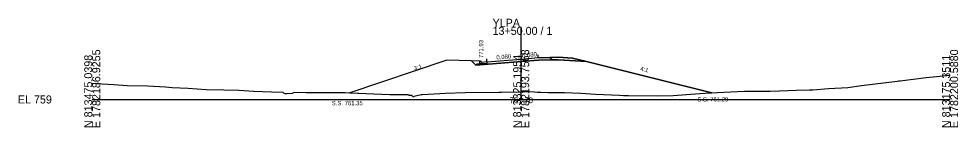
# Model space of a CAD drawing. Extents: x -76 to 1303, y -10 to 9544.
# Drawn here: x -25.7 to 302.8, y 3490.3 to 3528.2 of the extents above; entities that cross this region are included whole.
import ezdxf

# ---------------------------------------------------------------- set-up
doc = ezdxf.new("R2010")
doc.units = 0
for name, color, linetype in [('Exist Cross Section Cell', 7, 'Continuous'), ('Exist XS Center Line Elevation Label', 7, 'Continuous'), ('Exist XS Ground Line', 7, 'Continuous'), ('Prop XS Dump Level', 7, 'Continuous'), ('Prop XS Earthwork Shape', 7, 'Continuous'), ('Prop XS EOT Tick Mark', 7, 'Continuous'), ('Prop XS Finish Grade', 7, 'Continuous'), ('Prop XS Finish Grade CurbGutter', 7, 'Continuous'), ('Prop XS Finish Grade Earthwork', 7, 'Continuous'), ('Prop XS Finish Grade Paved Shoulder', 7, 'Continuous'), ('Prop XS Finish Grade Pavement', 7, 'Continuous'), ('Prop XS Hydro Elevations', 7, 'Continuous'), ('Prop XS Pvmt Edge Slope', 7, 'Continuous'), ('Prop XS SE Text', 7, 'Continuous'), ('Prop XS Side Slope Text', 7, 'Continuous'), ('Prop XS SS Elevation Text', 7, 'Continuous'), ('Prop XS Subgrade CurbGutter', 7, 'Continuous'), ('Prop XS Subgrade Earthwork', 7, 'Continuous'), ('Scratch_Level_3', 7, 'Continuous')]:
    doc.layers.add(name, color=color, linetype=linetype)

msp = doc.modelspace()

# ---------------------------------------------------------------- linework, layer by layer
at = {"layer": 'Exist Cross Section Cell'}
for p, q in [((150, 3500), (150, 3525.37)), ((0, 3500), (150, 3500)), ((150, 3500), (300, 3500))]:
    msp.add_line(p, q, dxfattribs=at)
at = {"layer": 'Exist XS Ground Line'}
for p, q in [((0, 3505.64), (1.39, 3505.58)), ((1.39, 3505.58), (7.54, 3505.21)), ((269, 3504.86), (281.44, 3506.4)), ((281.44, 3506.4), (282.06, 3506.48)), ((282.06, 3506.48), (282.5, 3506.53)), ((282.5, 3506.53), (291.68, 3507.67)), ((291.68, 3507.67), (300, 3508.46)), ((7.54, 3505.21), (12.25, 3504.91)), ((12.25, 3504.91), (19.31, 3504.73)), ((19.31, 3504.73), (25.63, 3504.38)), ((25.63, 3504.38), (27.94, 3504.15)), ((27.94, 3504.15), (33.5, 3503.96)), ((33.5, 3503.96), (39.79, 3503.5)), ((39.79, 3503.5), (45.96, 3503.41)), ((45.96, 3503.41), (51.38, 3503.19)), ((51.38, 3503.19), (56.36, 3502.88)), ((56.36, 3502.88), (62.74, 3502.68)), ((62.74, 3502.68), (66.64, 3502.6)), ((66.64, 3502.6), (66.99, 3502.18)), ((66.99, 3502.18), (67.32, 3502.03)), ((70.18, 3502.15), (70.39, 3502.39)), ((70.39, 3502.39), (70.9, 3502.52)), ((70.9, 3502.52), (74.79, 3502.45)), ((74.79, 3502.45), (84.25, 3502.37)), ((84.25, 3502.37), (86.65, 3502.47)), ((86.65, 3502.47), (88.42, 3502.43)), ((88.42, 3502.43), (95.71, 3502.05)), ((115.51, 3501.69), (123.57, 3502.23)), ((123.57, 3502.23), (130.36, 3502.41)), ((130.36, 3502.41), (142.26, 3502.58)), ((142.26, 3502.58), (142.64, 3502.58)), ((142.64, 3502.58), (143.14, 3502.59)), ((143.14, 3502.59), (150, 3502.7)), ((150, 3502.7), (152.94, 3502.74)), ((152.94, 3502.74), (154.66, 3502.62)), ((154.66, 3502.62), (155.73, 3502.56)), ((155.73, 3502.56), (156.9, 3502.51)), ((156.9, 3502.51), (159.44, 3502.41)), ((159.44, 3502.41), (165.19, 3502.4)), ((165.19, 3502.4), (170.85, 3502.22)), ((170.85, 3502.22), (176.01, 3501.83)), ((212.46, 3502.02), (216.12, 3502.26)), ((216.12, 3502.26), (228.15, 3502.92)), ((228.15, 3502.92), (228.54, 3502.93)), ((228.54, 3502.93), (237.11, 3502.93)), ((237.11, 3502.93), (240.37, 3503.05)), ((240.37, 3503.05), (246.17, 3503.22)), ((246.17, 3503.22), (250.78, 3503.36)), ((250.78, 3503.36), (251.95, 3503.38)), ((251.95, 3503.38), (257.44, 3503.79)), ((257.44, 3503.79), (264.28, 3504.17)), ((264.28, 3504.17), (269, 3504.86)), ((67.32, 3502.03), (68.05, 3502.09)), ((68.05, 3502.09), (70.18, 3502.15)), ((95.71, 3502.05), (104.12, 3501.78)), ((104.12, 3501.78), (109.53, 3501.71)), ((109.53, 3501.71), (110.6, 3501.68)), ((110.6, 3501.68), (110.66, 3501.53)), ((110.66, 3501.53), (111.71, 3501.49)), ((111.71, 3501.49), (111.79, 3501.29)), ((111.79, 3501.29), (112.48, 3500.94)), ((112.48, 3500.94), (112.59, 3501.19)), ((112.59, 3501.19), (113.5, 3501.39)), ((113.5, 3501.39), (114.61, 3501.6)), ((114.61, 3501.6), (115.05, 3501.77)), ((115.05, 3501.77), (115.11, 3501.69)), ((115.11, 3501.69), (115.51, 3501.69)), ((176.01, 3501.83), (184.36, 3501.5)), ((184.36, 3501.5), (185.78, 3501.43)), ((185.78, 3501.43), (187.49, 3501.37)), ((187.49, 3501.37), (197.84, 3501.23)), ((197.84, 3501.23), (203.18, 3501.38)), ((203.18, 3501.38), (212.46, 3502.02))]:
    msp.add_line(p, q, dxfattribs=at)
at = {"layer": 'Prop XS Dump Level'}
for p, q in [((138, 3513.17), (150, 3514.13)), ((150, 3514.13), (156, 3514.61))]:
    msp.add_line(p, q, dxfattribs=at)
at = {"layer": 'Prop XS Earthwork Shape'}
msp.add_lwpolyline([(216.12, 3502.26), (216.66, 3502.29), (172.83, 3513.24), (162.98, 3513.84), (160.9, 3513.79), (156.05, 3513.7), (150.07, 3513.22), (134.16, 3511.95), (132.61, 3513.49), (124, 3513.67), (90.03, 3502.35), (95.71, 3502.05), (104.12, 3501.78), (109.53, 3501.71), (110.6, 3501.68), (110.66, 3501.53), (111.71, 3501.49), (111.79, 3501.29), (112.48, 3500.94), (112.59, 3501.19), (113.5, 3501.39), (114.61, 3501.6), (115.05, 3501.77), (115.11, 3501.69), (115.51, 3501.69), (123.57, 3502.23), (130.36, 3502.41), (142.26, 3502.58), (142.64, 3502.58), (143.14, 3502.59), (150, 3502.7), (152.94, 3502.74), (154.66, 3502.62), (155.73, 3502.56), (156.9, 3502.51), (159.44, 3502.41), (165.19, 3502.4), (170.85, 3502.22), (176.01, 3501.83), (184.36, 3501.5), (185.78, 3501.43), (187.49, 3501.37), (197.84, 3501.23), (203.18, 3501.38), (212.46, 3502.02)], close=True, dxfattribs=at)
at = {"layer": 'Prop XS EOT Tick Mark'}
for p, q in [((156, 3514.61), (156, 3515.61)), ((138, 3513.17), (138, 3514.17))]:
    msp.add_line(p, q, dxfattribs=at)
at = {"layer": 'Prop XS Finish Grade'}
for p, q in [((135.5, 3513.43), (132.61, 3513.49)), ((160, 3514.69), (163, 3514.75)), ((163, 3514.75), (168, 3514.45)), ((168, 3514.45), (172.83, 3513.24))]:
    msp.add_line(p, q, dxfattribs=at)
at = {"layer": 'Prop XS Finish Grade CurbGutter'}
for p, q in [((135.5, 3513.43), (135.75, 3513.43)), ((135.75, 3513.43), (135.88, 3513.42)), ((135.97, 3513.33), (135.88, 3513.42)), ((136.03, 3513.08), (135.97, 3513.33)), ((136.13, 3512.99), (136.03, 3513.08)), ((136.25, 3512.96), (136.13, 3512.99)), ((138, 3513.17), (136.25, 3512.96))]:
    msp.add_line(p, q, dxfattribs=at)
at = {"layer": 'Prop XS Finish Grade Earthwork'}
for p, q in [((124, 3513.67), (90.03, 3502.35)), ((132.61, 3513.49), (124, 3513.67)), ((172.83, 3513.24), (216.66, 3502.29))]:
    msp.add_line(p, q, dxfattribs=at)
at = {"layer": 'Prop XS Finish Grade Paved Shoulder'}
msp.add_line((156, 3514.61), (160, 3514.69), dxfattribs=at)
at = {"layer": 'Prop XS Finish Grade Pavement'}
for p, q in [((138, 3513.17), (150, 3514.13)), ((150, 3514.13), (156, 3514.61))]:
    msp.add_line(p, q, dxfattribs=at)
at = {"layer": 'Prop XS Pvmt Edge Slope'}
for p, q in [((134.5, 3512.31), (134.16, 3511.95)), ((135.5, 3512.39), (134.5, 3512.31)), ((160, 3514.69), (160.9, 3513.79))]:
    msp.add_line(p, q, dxfattribs=at)
at = {"layer": 'Prop XS Subgrade CurbGutter'}
for p, q in [((135.5, 3512.39), (135.5, 3513.43)), ((138, 3512.59), (135.5, 3512.39)), ((138, 3513.17), (138, 3512.59))]:
    msp.add_line(p, q, dxfattribs=at)
at = {"layer": 'Prop XS Subgrade Earthwork'}
for p, q in [((134.16, 3511.95), (132.61, 3513.49)), ((134.16, 3511.95), (150.07, 3513.22)), ((150.07, 3513.22), (156.05, 3513.7)), ((156.05, 3513.7), (160.9, 3513.79)), ((160.9, 3513.79), (162.98, 3513.84)), ((162.98, 3513.84), (172.83, 3513.24))]:
    msp.add_line(p, q, dxfattribs=at)
at = {"layer": 'Scratch_Level_3'}
for p, q in [((163, 3514.75), (160, 3514.69)), ((160, 3514.69), (160.9, 3513.79)), ((160.9, 3513.79), (162.98, 3513.84)), ((162.98, 3513.84), (172.83, 3513.24)), ((168, 3514.45), (163, 3514.75)), ((172.83, 3513.24), (168, 3514.45))]:
    msp.add_line(p, q, dxfattribs=at)

# ---------------------------------------------------------------- texts
at = {"layer": 'Exist Cross Section Cell'}
for s, p in [('YLPA', (140, 3525.37)), ('13+50.00 / 1', (140, 3522.57)), ('EL 759', (-26, 3498.6))]:
    msp.add_text(s, height=2.8, dxfattribs=at).set_placement(p)
for s, p in [('N 813475.0398', (0, 3490)), ('E 1782186.9255', (2.8, 3490)), ('N 813325.1954', (150, 3490)), ('E 1782193.7568', (152.8, 3490)), ('N 813175.3511', (300, 3490)), ('E 1782200.5880', (302.8, 3490))]:
    msp.add_text(s, height=2.8, rotation=90, dxfattribs=at).set_placement(p)
at = {"layer": 'Exist XS Center Line Elevation Label'}
msp.add_text('761.70', height=2, dxfattribs=at).set_placement((145.95, 3498.7))
at = {"layer": 'Prop XS Dump Level'}
msp.add_text('Case4', height=0.04, dxfattribs=at).set_placement((168, 3514.41))
at = {"layer": 'Prop XS Hydro Elevations'}
msp.add_text('771.93', height=1.5, rotation=90, dxfattribs=at).set_placement((136.75, 3514.43))
at = {"layer": 'Prop XS SE Text'}
for p in [(141.38, 3513.94), (150.38, 3514.66)]:
    msp.add_text('0.080', height=1.5, rotation=4.5739, dxfattribs=at).set_placement(p)
at = {"layer": 'Prop XS Side Slope Text'}
for s, rotation, p in [('3:1', 17.8228, (112.73, 3510.08)), ('4:1', 345.9638, (191.52, 3510.12))]:
    msp.add_text(s, height=1.5, rotation=rotation, dxfattribs=at).set_placement(p)
at = {"layer": 'Prop XS SS Elevation Text'}
for s, p in [('S.S. 761.35', (83.77, 3497.97)), ('S.S. 761.29', (211.62, 3499.29))]:
    msp.add_text(s, height=1.5, dxfattribs=at).set_placement(p)

doc.saveas('drawing.dxf')
